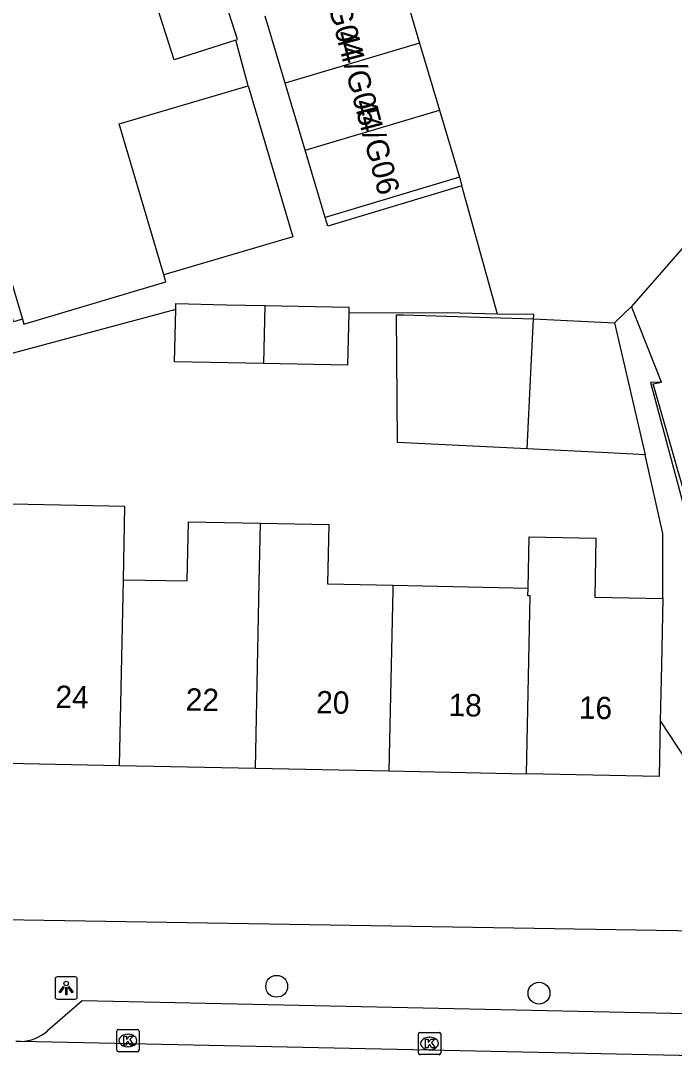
# Model space of a CAD drawing. Extents: x 162532 to 163264, y 381233 to 382042.
# Drawn here: x 162954.65 to 162983.93, y 381779.97 to 381826.43 of the extents above; entities that cross this region are included whole.
import ezdxf

# ---------------------------------------------------------------- set-up
doc = ezdxf.new("R2010")
doc.units = 0
for name, color, linetype in [('IMGEO_Boom', 7, 'Continuous'), ('IMGEO_Kolk', 7, 'Continuous'), ('IMGEO_Lichtpunt', 7, 'Continuous'), ('IMGEO_Pand', 7, 'Continuous'), ('IMGEO_Pand_nummerreeks', 7, 'Continuous'), ('IMGEO_Rijbaan_lokaal_open', 7, 'Continuous'), ('IMGEO_Voetpad_open', 7, 'Continuous')]:
    doc.layers.add(name, color=color, linetype=linetype)

msp = doc.modelspace()

# ---------------------------------------------------------------- linework, layer by layer
at = {"layer": 'IMGEO_Boom'}
for centre in [(162966.12, 381783.151), (162977.874, 381782.842)]:
    msp.add_circle(centre, 0.489, dxfattribs=at)
at = {"layer": 'IMGEO_Kolk'}
for p, q in [((162958.951, 381780.293), (162958.951, 381781.145)), ((162959.026, 381781.219), (162959.878, 381781.219)), ((162959.952, 381781.145), (162959.952, 381780.293)), ((162972.543, 381781.087), (162973.395, 381781.087)), ((162959.439, 381780.999), (162959.464, 381780.999)), ((162972.468, 381780.161), (162972.468, 381781.013)), ((162972.956, 381780.867), (162972.981, 381780.867)), ((162973.469, 381781.013), (162973.469, 381780.161)), ((162959.878, 381780.219), (162959.026, 381780.219)), ((162959.462, 381780.439), (162959.437, 381780.439)), ((162972.979, 381780.307), (162972.954, 381780.307)), ((162973.395, 381780.087), (162972.543, 381780.087))]:
    msp.add_line(p, q, dxfattribs=at)
for points in [[(162958.951, 381780.293), (162958.951, 381781.145)], [(162959.026, 381781.219), (162959.878, 381781.219)], [(162959.952, 381781.145), (162959.952, 381780.293)], [(162972.543, 381781.087), (162973.395, 381781.087)], [(162959.272, 381780.919), (162959.395, 381780.919), (162959.395, 381780.768), (162959.525, 381780.919), (162959.689, 381780.919), (162959.543, 381780.768), (162959.696, 381780.519), (162959.544, 381780.519), (162959.459, 381780.683), (162959.395, 381780.616), (162959.395, 381780.519), (162959.272, 381780.519), (162959.272, 381780.919)], [(162972.468, 381780.161), (162972.468, 381781.013)], [(162972.789, 381780.787), (162972.912, 381780.787), (162972.912, 381780.636), (162973.042, 381780.787), (162973.206, 381780.787), (162973.06, 381780.636), (162973.213, 381780.387), (162973.061, 381780.387), (162972.976, 381780.551), (162972.912, 381780.484), (162972.912, 381780.387), (162972.789, 381780.387), (162972.789, 381780.787)], [(162973.469, 381781.013), (162973.469, 381780.161)], [(162959.878, 381780.219), (162959.026, 381780.219)], [(162973.395, 381780.087), (162972.543, 381780.087)]]:
    msp.add_lwpolyline(points, dxfattribs=at)
for centre, start, end in [((162959.028, 381781.143), 91.552, 178.448), ((162959.028, 381781.143), 91.552, 178.448), ((162959.876, 381781.143), 1.552, 88.448), ((162959.876, 381781.143), 1.552, 88.448), ((162972.545, 381781.011), 91.552, 178.448), ((162972.545, 381781.011), 91.552, 178.448), ((162973.393, 381781.011), 1.552, 88.448), ((162973.393, 381781.011), 1.552, 88.448), ((162959.028, 381780.295), 181.552, 268.448), ((162959.028, 381780.295), 181.552, 268.448), ((162959.876, 381780.295), 271.552, 358.448), ((162959.876, 381780.295), 271.552, 358.448), ((162972.545, 381780.163), 181.552, 268.448), ((162972.545, 381780.163), 181.552, 268.448), ((162973.393, 381780.163), 271.552, 358.448), ((162973.393, 381780.163), 271.552, 358.448)]:
    msp.add_arc(centre, 0.0765, start, end, dxfattribs=at)
for centre, major_axis, ratio, start_param, end_param in [((162959.438, 381780.719), (-0.387, 0.002), 0.722429, 4.712389, 7.853982), ((162959.463, 381780.719), (-0.39, 0.002), 0.717154, 1.570796, 4.712389), ((162972.955, 381780.587), (-0.387, 0.002), 0.722429, 4.712389, 7.853982), ((162972.98, 381780.587), (-0.39, 0.002), 0.717154, 1.570796, 4.712389)]:
    msp.add_ellipse(centre, major_axis=major_axis, ratio=ratio, start_param=start_param, end_param=end_param, dxfattribs=at)
at = {"layer": 'IMGEO_Lichtpunt'}
for p, q in [((162956.188, 381783.48), (162956.188, 381782.673)), ((162956.188, 381783.48), (162956.188, 381782.673)), ((162957.09, 381783.575), (162956.282, 381783.575)), ((162957.09, 381783.575), (162956.282, 381783.575)), ((162957.184, 381782.673), (162957.184, 381783.48)), ((162957.184, 381782.673), (162957.184, 381783.48)), ((162956.282, 381782.579), (162957.09, 381782.579)), ((162956.282, 381782.579), (162957.09, 381782.579))]:
    msp.add_line(p, q, dxfattribs=at)
for points in [[(162956.562, 381783.144), (162956.601, 381783.116), (162956.413, 381782.854), (162956.375, 381782.881), (162956.562, 381783.144)], [(162956.664, 381783.096), (162956.711, 381783.096), (162956.711, 381782.774), (162956.664, 381782.774), (162956.664, 381783.096)], [(162956.774, 381783.116), (162956.812, 381783.143), (162956.999, 381782.881), (162956.96, 381782.853), (162956.774, 381783.116)]]:
    msp.add_lwpolyline(points, dxfattribs=at)
msp.add_circle((162956.687, 381783.278), 0.0994, dxfattribs=at)
for centre, start, end in [((162956.282, 381783.48), 90, 180), ((162956.282, 381783.48), 90, 180), ((162957.09, 381783.48), 0, 90), ((162957.09, 381783.48), 0, 90), ((162956.282, 381782.673), 180, 270), ((162956.282, 381782.673), 180, 270), ((162957.09, 381782.673), 270, 0), ((162957.09, 381782.673), 270, 360)]:
    msp.add_arc(centre, 0.0946, start, end, dxfattribs=at)
at = {"layer": 'IMGEO_Pand'}
for points in [[(162964.294, 381825.56), (162964.364, 381825.582), (162962.829, 381830.391)], [(162964.294, 381825.56), (162961.523, 381824.675), (162959.988, 381829.484), (162960.213, 381829.556)], [(162971.631, 381828.43), (162972.525, 381825.423)], [(162966.495, 381823.63), (162965.601, 381826.636)], [(162972.525, 381825.423), (162966.495, 381823.63)], [(162972.525, 381825.423), (162973.42, 381822.417)], [(162961.058, 381815.037), (162959.061, 381821.808), (162964.842, 381823.514)], [(162964.842, 381823.514), (162966.84, 381816.742), (162961.058, 381815.037)], [(162967.39, 381820.623), (162966.495, 381823.63)], [(162967.39, 381820.623), (162973.42, 381822.417)], [(162973.42, 381822.417), (162974.314, 381819.41)], [(162968.284, 381817.616), (162967.39, 381820.623)], [(162952.49, 381820.574), (162954.728, 381813.049)], [(162974.314, 381819.41), (162968.284, 381817.616)], [(162985.336, 381817.41), (162982.022, 381813.624)], [(162961.594, 381813.486), (162961.599, 381813.748), (162963.852, 381813.702), (162965.582, 381813.665)], [(162965.582, 381813.665), (162965.528, 381811.063)], [(162965.582, 381813.665), (162969.35, 381813.585), (162969.345, 381813.325)], [(162983.367, 381810.236), (162982.022, 381813.624)], [(162954.728, 381813.049), (162954.329, 381812.93), (162954.218, 381813.304), (162951.951, 381812.63), (162947.158, 381811.205), (162947.276, 381810.809), (162946.922, 381810.704)], [(162965.528, 381811.063), (162961.545, 381811.145), (162961.594, 381813.486)], [(162969.345, 381813.325), (162969.297, 381810.985), (162965.528, 381811.063)], [(162977.342, 381807.234), (162971.525, 381807.523), (162971.482, 381813.251), (162971.808, 381813.241), (162977.631, 381813.068)], [(162990.032, 381813.364), (162987.237, 381810.048), (162986.545, 381809.368), (162988.717, 381806.619), (162986.441, 381806.016), (162984.331, 381805.458), (162984.083, 381806.325), (162983.946, 381806.806), (162982.987, 381810.157), (162983.367, 381810.236)], [(162977.342, 381807.234), (162977.511, 381810.647), (162977.631, 381813.068)], [(162977.631, 381813.068), (162981.26, 381812.888)], [(162981.26, 381812.888), (162982.623, 381806.972)], [(162982.623, 381806.972), (162980.971, 381807.054), (162977.342, 381807.234)], [(162959.247, 381801.376), (162959.314, 381804.662), (162952.08, 381804.81), (162951.914, 381796.703)], [(162959.247, 381801.376), (162962.114, 381801.317), (162962.169, 381803.976), (162965.39, 381803.91)], [(162965.164, 381792.927), (162965.335, 381801.251), (162965.39, 381803.91)], [(162965.39, 381803.91), (162968.45, 381803.847), (162968.395, 381801.188), (162971.325, 381801.128)], [(162977.384, 381801.003), (162977.43, 381803.292), (162980.425, 381803.23), (162980.372, 381800.593), (162983.417, 381800.53)], [(162959.075, 381793.053), (162959.247, 381801.376)], [(162971.325, 381801.128), (162971.317, 381800.928), (162971.15, 381792.804)], [(162971.325, 381801.128), (162977.384, 381801.003)], [(162977.318, 381792.677), (162977.482, 381800.653), (162977.377, 381800.655), (162977.384, 381801.003)], [(162983.417, 381800.53), (162983.356, 381797.554), (162983.304, 381795.054)], [(162983.304, 381795.054), (162983.253, 381792.555), (162977.318, 381792.677)], [(162954.052, 381793.156), (162959.075, 381793.053)], [(162959.075, 381793.053), (162965.164, 381792.927)], [(162965.164, 381792.927), (162971.15, 381792.804)], [(162971.15, 381792.804), (162977.318, 381792.677)]]:
    msp.add_lwpolyline(points, dxfattribs=at)
at = {"layer": 'IMGEO_Rijbaan_lokaal_open'}
for points in [[(162974.314, 381819.41), (162974.42, 381819.027)], [(162976.006, 381813.283), (162974.42, 381819.027)], [(162982.022, 381813.624), (162981.26, 381812.888)], [(162977.631, 381813.068), (162977.637, 381813.261), (162976.006, 381813.283)], [(162954.65, 381780.67), (162954.429, 381780.672)], [(162987.671, 381779.97), (162954.65, 381780.67)]]:
    msp.add_lwpolyline(points, dxfattribs=at)
at = {"layer": 'IMGEO_Voetpad_open'}
for points in [[(162964.842, 381823.514), (162964.294, 381825.56)], [(162974.42, 381819.027), (162968.414, 381817.216), (162968.284, 381817.616)], [(162954.728, 381813.049), (162954.788, 381812.826), (162961.15, 381814.729), (162961.058, 381815.037)], [(162961.594, 381813.486), (162953.229, 381811.245)], [(162976.006, 381813.283), (162973.753, 381813.329), (162969.345, 381813.325)], [(162983.367, 381810.236), (162982.867, 381810.21), (162984.165, 381805.367), (162984.495, 381804.134), (162984.608, 381796.596)], [(162983.417, 381800.53), (162983.417, 381803.449), (162982.623, 381806.972)], [(162983.304, 381795.054), (162989.552, 381785.568)], [(162953.874, 381786.148), (162989.552, 381785.568)], [(162986.595, 381780.417), (162985.19, 381781.898), (162957.409, 381782.505), (162955.854, 381781.153)]]:
    msp.add_lwpolyline(points, dxfattribs=at)
msp.add_arc((162954.526, 381782.722), 2.056, 273.4666, 310.251, dxfattribs=at)

# ---------------------------------------------------------------- texts
at = {"layer": 'IMGEO_Pand_nummerreeks'}
for s, rotation, p in [('44/G04', 284.8476, (162967.948, 381828.891)), ('44/G05', 284.8476, (162968.743, 381825.871)), ('44/G06', 284.8476, (162969.569, 381822.787)), ('24', 358.8197, (162956.199, 381795.632)), ('22', 358.8209, (162962.035, 381795.512)), ('20', 358.8209, (162967.881, 381795.392)), ('18', 358.8209, (162973.812, 381795.27)), ('16', 358.8197, (162979.651, 381795.149))]:
    msp.add_text(s, height=1, rotation=rotation, dxfattribs=at).set_placement(p)

doc.saveas('drawing.dxf')
